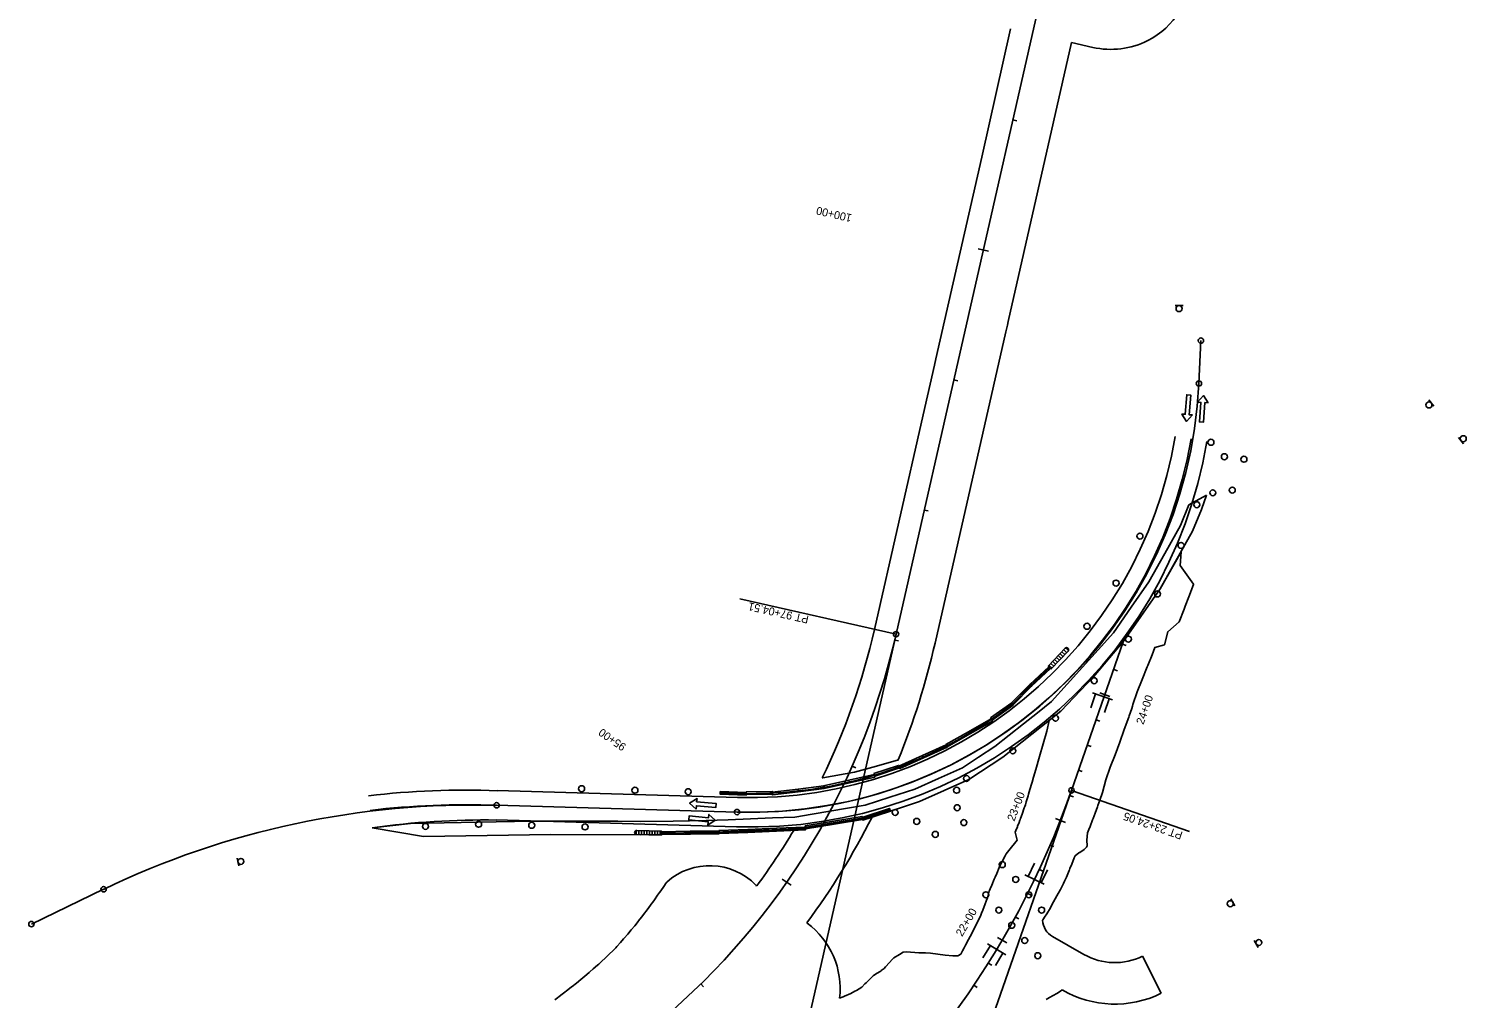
# Model space of a CAD drawing. Extents: x 1710760 to 1712674, y 548603 to 551129.
# Drawn here: x 1711597 to 1712674, y 549354 to 550081 of the extents above; entities that cross this region are included whole.
import ezdxf

# ---------------------------------------------------------------- set-up
doc = ezdxf.new("R2010")
doc.units = 0
for name, color, linetype in [('R_Horz Alg', 7, 'Continuous'), ('R_Horz Alg Annot', 7, 'Continuous'), ('R_MOT', 7, 'Continuous'), ('R_No Plot', 7, 'Continuous'), ('R_Striping', 7, 'Continuous')]:
    doc.layers.add(name, color=color, linetype=linetype)

msp = doc.modelspace()

# ---------------------------------------------------------------- linework, layer by layer
at = {"layer": 'R_Horz Alg'}
for p, q in [((1712246.8, 549627.3), (1712450.8, 550525.8)), ((1712246.8, 549627.3), (1712450.8, 550525.8)), ((1712473.8, 549815.3), (1712475.3, 549847.4)), ((1712378.3, 549510.2), (1712417.1, 549621.6)), ((1711947.4, 549499), (1712127.6, 549493.9)), ((1711598.7, 549409.9), (1711652.8, 549436))]:
    msp.add_line(p, q, dxfattribs=at)
for centre, radius, start, end in [((1712137.1, 549830.8), 337, 268.3826, 357.3716), ((1711727, 549745.3), 533, 270.6428, 347.2066), ((1711727, 549745.3), 533, 270.6428, 347.2066), ((1711777.2, 549719.9), 636.6, 271.0787, 340.7734), ((1711929.4, 548862.6), 636.6, 88.3826, 115.7513)]:
    msp.add_arc(centre, radius, start, end, dxfattribs=at)
at = {"layer": 'R_Horz Alg Annot'}
for p, q in [((1712153.6, 549217.1), (1712246.8, 549627.3)), ((1712153.6, 549217.1), (1712246.8, 549627.3)), ((1712232.3, 549091.7), (1712378.3, 549510.2)), ((1712466.6, 549479.4), (1712378.3, 549510.2))]:
    msp.add_line(p, q, dxfattribs=at)
for points in [[(1712337.3, 550012.3), (1712334.3, 550013)], [(1712308.3, 549916.3), (1712316.1, 549914.5)], [(1712293, 549817.3), (1712290.1, 549817.9)], [(1712270.8, 549719.7), (1712267.9, 549720.4)], [(1712246.8, 549627.3), (1712129.8, 549653.9)], [(1712248.7, 549622.2), (1712245.8, 549622.9)], [(1712419.3, 549618.7), (1712416.5, 549619.7)], [(1712412.7, 549599.8), (1712409.9, 549600.8)], [(1712399.5, 549583.3), (1712407.1, 549580.6)], [(1712399.5, 549562.1), (1712396.7, 549563.1)], [(1712393, 549543.2), (1712390.1, 549544.2)], [(1712216.6, 549527.1), (1712213.8, 549528.3)], [(1712386.4, 549524.3), (1712383.5, 549525.3)], [(1712379.8, 549505.4), (1712376.9, 549506.4)], [(1712366.2, 549489.1), (1712373.7, 549486.2)], [(1712365.1, 549468), (1712362.4, 549469.2)], [(1712356.9, 549449.7), (1712354.2, 549450.9)], [(1712161.5, 549443.6), (1712168.1, 549439)], [(1712348.1, 549431.6), (1712345.5, 549432.9)], [(1712338.8, 549413.8), (1712336.2, 549415.2)], [(1712322.9, 549399.8), (1712329.8, 549395.8)], [(1712318.5, 549379.1), (1712315.9, 549380.7)], [(1712102.5, 549362.8), (1712100.4, 549365)], [(1712307.5, 549362.3), (1712305, 549364)]]:
    msp.add_lwpolyline(points, dxfattribs=at)
for centre in [(1712475.3, 549847.4), (1712473.8, 549815.3), (1712246.8, 549627.3), (1712246.8, 549627.3), (1712378.3, 549510.2), (1711947.4, 549499), (1712127.6, 549493.9), (1711652.8, 549436), (1711598.7, 549409.9)]:
    msp.add_circle(centre, 2, dxfattribs=at)
at = {"layer": 'R_MOT'}
for p, q in [((1712311, 549985), (1712332.5, 550081.3)), ((1712311, 549985), (1712332.5, 550081.3)), ((1712378.3, 550070.9), (1712364.8, 550011.4)), ((1712378.3, 550070.9), (1712364.8, 550011.4)), ((1712394.2, 550067.3), (1712378.3, 550070.9)), ((1712394.2, 550067.3), (1712378.3, 550070.9)), ((1712364.8, 550011.4), (1712330.8, 549861.8)), ((1712364.8, 550011.4), (1712330.8, 549861.8)), ((1712276.6, 549833.7), (1712311, 549985)), ((1712276.6, 549833.7), (1712311, 549985)), ((1712455.9, 549873.7), (1712461.9, 549873.7)), ((1712330.8, 549861.8), (1712330.2, 549859)), ((1712330.8, 549861.8), (1712330.2, 549859)), ((1712329.1, 549854.1), (1712276, 549620.6)), ((1712329.1, 549854.1), (1712276, 549620.6)), ((1712330.2, 549859), (1712329.1, 549854.1)), ((1712330.2, 549859), (1712329.1, 549854.1)), ((1712267.1, 549791.8), (1712275.6, 549828.9)), ((1712267.1, 549791.8), (1712275.6, 549828.9)), ((1712275.6, 549828.9), (1712276.6, 549833.7)), ((1712275.6, 549828.9), (1712276.6, 549833.7)), ((1712646, 549803), (1712649.8, 549798.4)), ((1712230.6, 549630.9), (1712267.1, 549791.8)), ((1712230.6, 549630.9), (1712267.1, 549791.8)), ((1712672.1, 549770.1), (1712668.3, 549774.8)), ((1712466.2, 549724.2), (1712479.4, 549731.6)), ((1712466.2, 549724.2), (1712479.4, 549731.6)), ((1712460.4, 549689.1), (1712459.7, 549678.8)), ((1712369.7, 549612.6), (1712371.9, 549610.6)), ((1712371.1, 549614.1), (1712373.3, 549612.1)), ((1712372.5, 549615.6), (1712374.6, 549613.5)), ((1712373.9, 549617), (1712376, 549615)), ((1712347.4, 549588.6), (1712362, 549602.2)), ((1712361.5, 549603.9), (1712363.7, 549601.8)), ((1712362.9, 549605.4), (1712365.1, 549603.3)), ((1712364.3, 549606.8), (1712366.4, 549604.8)), ((1712365.6, 549608.3), (1712367.8, 549606.2)), ((1712367, 549609.7), (1712369.2, 549607.7)), ((1712368.4, 549611.2), (1712370.5, 549609.1)), ((1712333.2, 549574.3), (1712347.4, 549588.6)), ((1712392.7, 549572.2), (1712396.3, 549582.5)), ((1712409, 549578), (1712393.9, 549583.3)), ((1712333.2, 549574.3), (1712333.2, 549574.3)), ((1712402.9, 549568.6), (1712406.5, 549578.9)), ((1712115, 549508.3), (1712128, 549507.9)), ((1712051.9, 549480), (1712051.9, 549477.2)), ((1712053.9, 549480), (1712053.9, 549477)), ((1712055.9, 549480), (1712055.9, 549477)), ((1712057.9, 549479.9), (1712057.9, 549476.9)), ((1712059.9, 549479.9), (1712059.9, 549476.9)), ((1712061.9, 549479.8), (1712061.9, 549476.8)), ((1712063.9, 549479.8), (1712063.9, 549476.8)), ((1712065.9, 549479.7), (1712065.9, 549476.7)), ((1712067.9, 549479.7), (1712067.9, 549476.7)), ((1712069.9, 549479.6), (1712069.9, 549476.6)), ((1712331.3, 549465.1), (1712337.6, 549472.9)), ((1711754.2, 549453.5), (1711752.9, 549459.4)), ((1712350.5, 549455.5), (1712345.7, 549445.6)), ((1712360.3, 549450.7), (1712355.5, 549440.9)), ((1712343.4, 549446.8), (1712357.8, 549439.8)), ((1712141.8, 549438.9), (1712142.4, 549438.5)), ((1712497.7, 549428.9), (1712500.8, 549423.7)), ((1712179.9, 549410.8), (1712180.1, 549410.6)), ((1712364.1, 549400.6), (1712387.6, 549387.2)), ((1712518.3, 549392.4), (1712515.2, 549397.5)), ((1712311.9, 549384.5), (1712317.5, 549393.8)), ((1712329.1, 549386.9), (1712315.4, 549395.1)), ((1712321.2, 549378.9), (1712326.8, 549388.2)), ((1712431.6, 549385.9), (1712445.4, 549358))]:
    msp.add_line(p, q, dxfattribs=at)
for points in [[(1712468.9, 549791.7), (1712464.5, 549786.9), (1712461, 549792.4), (1712463.5, 549792.2), (1712464.7, 549806.8), (1712467.7, 549806.6), (1712466.4, 549791.9)], [(1712480.8, 549800.7), (1712477.2, 549806.2), (1712472.8, 549801.3), (1712475.3, 549801.1), (1712474.1, 549786.5), (1712477.1, 549786.2), (1712478.3, 549800.9)], [(1712347, 549589.6), (1712361.3, 549602.9), (1712362.6, 549601.5), (1712348.4, 549588.2)], [(1712333.2, 549575.8), (1712347, 549589.6), (1712348.4, 549588.2), (1712334.6, 549574.4)], [(1712317.5, 549564.5), (1712333.5, 549575.8), (1712334.6, 549574.2), (1712318.7, 549562.9)], [(1712301.2, 549554.2), (1712318.1, 549563.9), (1712319, 549562.2), (1712302.1, 549552.5)], [(1712284.2, 549544.5), (1712301.2, 549554.2), (1712302.1, 549552.5), (1712285.2, 549542.8)], [(1712248.8, 549528.4), (1712266.6, 549536.4), (1712267.4, 549534.6), (1712249.6, 549526.7)], [(1712266.6, 549536.4), (1712284.4, 549544.3), (1712285.2, 549542.6), (1712267.4, 549534.6)], [(1712230.2, 549522.8), (1712248.7, 549528.9), (1712249.4, 549527.1), (1712230.9, 549520.9)], [(1712192.5, 549513.5), (1712211.5, 549517.8), (1712212, 549515.9), (1712192.9, 549511.6)], [(1712211.5, 549517.8), (1712230.5, 549522), (1712231, 549520.1), (1712212, 549515.9)], [(1712096.9, 549496.1), (1712092, 549500.5), (1712097.6, 549504), (1712097.3, 549501.6), (1712112, 549500.3), (1712111.7, 549497.3), (1712097.1, 549498.6)], [(1712115, 549509.3), (1712134.5, 549508.6), (1712134.5, 549506.7), (1712115, 549507.3)], [(1712134.5, 549509), (1712154, 549509.4), (1712154, 549507.4), (1712134.5, 549507)], [(1712153.9, 549508.8), (1712173.3, 549511.1), (1712173.5, 549509.2), (1712154.1, 549506.8)], [(1712173.3, 549511.1), (1712192.6, 549513.5), (1712192.9, 549511.5), (1712173.5, 549509.2)], [(1712221.3, 549489.9), (1712241.8, 549496.6), (1712242.5, 549494.6), (1712222, 549487.8)], [(1712105.8, 549484.2), (1712111.3, 549487.8), (1712106.5, 549492.2), (1712106.3, 549489.7), (1712091.6, 549491), (1712091.4, 549488), (1712106, 549486.7)], [(1712157.2, 549481.8), (1712178.9, 549482.6), (1712178.9, 549480.5), (1712157.3, 549479.6)], [(1712178.6, 549483.5), (1712200, 549487), (1712200.3, 549484.9), (1712179, 549481.4)], [(1712200, 549487), (1712221.3, 549490.6), (1712221.7, 549488.4), (1712200.3, 549484.9)], [(1712070.8, 549479.2), (1712092.4, 549479.5), (1712092.5, 549477.3), (1712070.9, 549477)], [(1712092.4, 549479.5), (1712114.1, 549479.7), (1712114.1, 549477.6), (1712092.5, 549477.3)], [(1712114, 549480), (1712135.6, 549480.9), (1712135.7, 549478.7), (1712114.1, 549477.8)], [(1712135.6, 549480.9), (1712157.2, 549481.8), (1712157.3, 549479.6), (1712135.7, 549478.7)]]:
    msp.add_lwpolyline(points, close=True, dxfattribs=at)
for points in [[(1712479.4, 549731.6), (1712475.6, 549720.7), (1712469, 549704.5), (1712444.8, 549661.3), (1712417.6, 549622.2), (1712394.7, 549595.2), (1712370.3, 549569.5), (1712326.8, 549535), (1712301.3, 549518.4), (1712264.4, 549501.9), (1712226, 549489.2), (1712171.9, 549480.3), (1712104.7, 549477.5), (1712055.1, 549476.9), (1711988.1, 549477.2), (1711892.6, 549475.7), (1711854.2, 549482.1)], [(1712479.4, 549731.6), (1712466.2, 549724.2)], [(1711854.2, 549482.1), (1711882.9, 549485.3), (1711895.5, 549485.6), (1711908.2, 549485.9), (1711920.8, 549486.1), (1711933.4, 549486.4), (1711947, 549486.6), (1711960.7, 549486.8), (1711974.4, 549487), (1711988, 549487.2), (1712004.8, 549487.1), (1712021.5, 549487.1), (1712038.3, 549487), (1712055, 549486.9), (1712079.7, 549487.2), (1712104.4, 549487.5), (1712121, 549488.2), (1712137.6, 549488.9), (1712154.2, 549489.6), (1712170.8, 549490.2), (1712184, 549492.4), (1712197.2, 549494.6), (1712210.4, 549496.8), (1712223.6, 549499), (1712242.2, 549505.1), (1712260.8, 549511.2), (1712278.6, 549519.2), (1712296.5, 549527.2), (1712308.7, 549535.2), (1712320.9, 549543.1), (1712331.6, 549551.5), (1712342.2, 549560), (1712352.8, 549568.4), (1712363.4, 549576.8), (1712375, 549589.7), (1712386.6, 549602.6), (1712398.2, 549615.5), (1712409.8, 549628.4), (1712423.1, 549647.5), (1712436.3, 549666.6), (1712448.2, 549687.7), (1712460, 549708.8), (1712466.2, 549724.2)], [(1712361.6, 549562.6), (1712370.3, 549569.5), (1712394.7, 549595.2), (1712417.6, 549622.2), (1712444.8, 549661.3), (1712460.4, 549689.1)], [(1712459.7, 549678.8), (1712469.8, 549664.7), (1712469.8, 549664.6), (1712466.3, 549655.3), (1712463.5, 549648.2), (1712462.7, 549646), (1712459.1, 549636.6), (1712450.4, 549629.1), (1712448.1, 549619.3)], [(1712448.1, 549619.3), (1712440.7, 549617.4), (1712438.8, 549611.9), (1712435.4, 549603.8), (1712435, 549602.7), (1712431.2, 549593.4), (1712427.5, 549584.1), (1712424.3, 549574.6), (1712424.3, 549574.5), (1712424, 549573.4), (1712423.4, 549571.6), (1712421.6, 549566.2), (1712421.2, 549565.1), (1712417.7, 549555.8), (1712414.4, 549546.3), (1712410.9, 549536.9), (1712407.3, 549527.6), (1712404.1, 549518.1), (1712401.4, 549508.5), (1712399.5, 549502.9), (1712398.1, 549498.9), (1712397.7, 549497.9), (1712395.9, 549493), (1712394.5, 549489.2), (1712394.1, 549488.1), (1712392.2, 549483.2), (1712391.3, 549480.8), (1712390.8, 549479.5), (1712390.3, 549478.3), (1712389.8, 549472.9), (1712389.9, 549468.7), (1712389.4, 549467.7), (1712389.3, 549467.4), (1712389.3, 549467.4), (1712387.7, 549465.9), (1712384.5, 549463.7), (1712384.3, 549463.6), (1712383.9, 549463.3), (1712383.9, 549463.3), (1712381, 549461.2), (1712380.4, 549459.7), (1712378.5, 549454.9), (1712377.1, 549451.6), (1712376.7, 549450.7), (1712376.5, 549450.1), (1712374.5, 549445.2), (1712373.1, 549442.1), (1712372.4, 549440.4), (1712370, 549435.8), (1712368.4, 549432.9), (1712367.4, 549431.2), (1712364.9, 549426.7), (1712363.4, 549423.8), (1712362.5, 549422), (1712359.8, 549417.7), (1712359.7, 549417.6), (1712358.1, 549415), (1712357.3, 549413.8), (1712356.9, 549413.2), (1712356.6, 549412.8)], [(1712373.5, 549616.7), (1712360.9, 549603.2), (1712363.1, 549601.2), (1712375.7, 549614.6)], [(1712337.6, 549472.9), (1712336.1, 549478.9), (1712336.6, 549480.2), (1712337.7, 549482.8), (1712337.7, 549482.9), (1712337.8, 549483.2), (1712337.9, 549483.4), (1712339, 549486.2), (1712339.6, 549487.9), (1712339.6, 549487.9), (1712339.7, 549488.1), (1712340.1, 549489.1), (1712341.2, 549492.4), (1712342.8, 549497), (1712343.2, 549498.1), (1712343.7, 549499.4), (1712344.4, 549501.6), (1712345.8, 549506.2), (1712346.1, 549507.3), (1712347.1, 549510.9), (1712348.5, 549515.5), (1712348.8, 549516.4), (1712349.8, 549520.2), (1712351.5, 549525.9), (1712354.2, 549535.5), (1712357, 549545.1), (1712359.8, 549554.7), (1712361.6, 549562.6)], [(1712248.5, 549533.1), (1712232.1, 549528.4), (1712215.7, 549523.8), (1712191.9, 549519.6), (1712191.4, 549519.5)], [(1712248.5, 549533.1), (1712232.1, 549528.4), (1712215.7, 549523.8), (1712191.9, 549519.6), (1712191.4, 549519.5)], [(1712242.2, 549495.6), (1712225.7, 549490.2), (1712171.8, 549481.3), (1712104.7, 549478.5), (1712070.8, 549478.1)], [(1712170.2, 549480.2), (1712171.9, 549480.3), (1712226, 549489.2), (1712228.9, 549490.2)], [(1712052.4, 549480.1), (1712070.9, 549479.6), (1712070.8, 549476.6), (1712052.3, 549477.1)], [(1712293.1, 549386), (1712295.3, 549387.4), (1712296.6, 549389.8), (1712297.9, 549392.1), (1712298.9, 549394.1), (1712301.2, 549398.4), (1712302.4, 549400.6), (1712303.5, 549402.8), (1712305.7, 549407.1), (1712306.8, 549409.3), (1712307.9, 549411.5), (1712310, 549415.9), (1712310.9, 549418), (1712311.9, 549420.4), (1712313.6, 549425.1), (1712314.4, 549427.1), (1712314.6, 549427.9), (1712315.3, 549429.7), (1712316.6, 549434.5), (1712316.9, 549435.1), (1712317.4, 549436.4), (1712318.5, 549439), (1712318.5, 549439.1), (1712320.3, 549443.5), (1712321.1, 549445.2), (1712322.2, 549447.9), (1712324.1, 549452.4), (1712324.8, 549454.1), (1712326.3, 549456.8), (1712328.5, 549461), (1712329.3, 549462.5), (1712331.3, 549465.1)], [(1712036.7, 549392.2), (1712037.6, 549393.2), (1712040.3, 549396.2), (1712042.5, 549398.8), (1712043, 549399.3), (1712045.7, 549402.4), (1712048.3, 549405.6), (1712048.3, 549405.6), (1712050.9, 549408.7), (1712053.4, 549411.9), (1712053.8, 549412.4), (1712056, 549415.1), (1712058.5, 549418.3), (1712059.2, 549419.4), (1712060.9, 549421.6), (1712063.3, 549424.9), (1712064.5, 549426.4), (1712065.7, 549428.2), (1712068, 549431.5), (1712069.5, 549433.6), (1712070.4, 549434.8), (1712072.7, 549438.1), (1712074.5, 549440.8), (1712074.9, 549441.4)], [(1711991, 549353.2), (1711993.1, 549354.7), (1711994.3, 549355.7), (1711996.6, 549357.4), (1711997.6, 549358.1), (1712000.9, 549360.6), (1712003.6, 549362.8), (1712004.1, 549363.1), (1712007.3, 549365.7), (1712010.5, 549368.3), (1712010.5, 549368.3), (1712013.6, 549370.9), (1712016.7, 549373.6), (1712017.3, 549374.1), (1712019.8, 549376.3), (1712022.9, 549379), (1712023.9, 549379.9), (1712025.9, 549381.8), (1712028.9, 549384.6), (1712030.4, 549386), (1712031.8, 549387.4), (1712034.7, 549390.2), (1712036.7, 549392.2)], [(1712204.5, 549354.4), (1712207.1, 549355.4), (1712208.2, 549355.9), (1712212.8, 549357.9), (1712216, 549359.5), (1712217.1, 549360.2), (1712221.2, 549362.7), (1712223.5, 549365), (1712224.3, 549365.8), (1712224.4, 549365.9), (1712227.6, 549369.2), (1712229.8, 549371.4), (1712229.8, 549371.4), (1712231.1, 549372.2), (1712232.1, 549372.8), (1712235.3, 549374.7), (1712235.7, 549375), (1712237.8, 549376.6), (1712238.8, 549377.8), (1712241.9, 549381.2), (1712243.9, 549383.4), (1712245.2, 549384.5), (1712249.4, 549387.1), (1712252, 549388.8), (1712254.7, 549389.1), (1712263.9, 549388.4), (1712264.5, 549388.4), (1712268.8, 549388.4), (1712272.7, 549388.1), (1712283.6, 549386.6), (1712289.4, 549386.1), (1712293.1, 549386)], [(1712371.4, 549360.6), (1712370.1, 549359.5), (1712367.4, 549357.8), (1712361.8, 549354.8), (1712359.4, 549353.4)]]:
    msp.add_lwpolyline(points, dxfattribs=at)
for centre in [(1712458.9, 549871.4), (1712646.2, 549799.2), (1712482.8, 549771.2), (1712671.9, 549773.9), (1712492.9, 549760.4), (1712507.5, 549758.5), (1712484.2, 549733.3), (1712498.8, 549735.3), (1712472.2, 549724.4), (1712429.6, 549700.8), (1712460.4, 549693.8), (1712411.7, 549665.6), (1712442.7, 549657.5), (1712389.9, 549633.2), (1712420.9, 549623.6), (1712395.3, 549592.4), (1712366.3, 549564.3), (1712334.3, 549539.8), (1712299.6, 549519.1), (1712011.1, 549511.4), (1712051.1, 549510.3), (1712091, 549509.2), (1712292.2, 549510.3), (1712246.1, 549493.6), (1712292.6, 549497.2), (1711894.1, 549483.2), (1711933.9, 549484.8), (1711973.7, 549484), (1712013.7, 549482.8), (1712262.3, 549486.9), (1712297.6, 549486), (1712276.2, 549477.2), (1711755.7, 549456.9), (1712326.4, 549454.5), (1712336.5, 549443.4), (1712314.1, 549431.9), (1712346.3, 549431.9), (1712323.8, 549420.4), (1712355.9, 549420.4), (1712497.3, 549425.2), (1712333.5, 549409), (1712343.2, 549397.6), (1712518.7, 549396.1), (1712353, 549386.2)]:
    msp.add_circle(centre, 2.25, dxfattribs=at)
for centre, radius, start, end in [((1712407.7, 550126.9), 61.1, 297.0662, 358.1873), ((1712407.7, 550126.9), 61.1, 297.0662, 358.1873), ((1712407.7, 550126.9), 61.1, 257.2066, 297.0662), ((1712407.7, 550126.9), 61.1, 257.2066, 297.0662), ((1711727, 549745.3), 516.4, 334.0724, 347.196), ((1711727, 549745.3), 516.4, 334.0724, 347.196), ((1711727, 549745.3), 563, 337.855, 347.1969), ((1711727, 549745.3), 563, 337.855, 347.1969), ((1712374.6, 549615.7), 1.5, 316.843, 136.843), ((1712137.4, 549828.7), 321, 268.3287, 307.5861), ((1711727, 549745.3), 563, 323.5493, 333.0539), ((1712052.3, 549478.6), 1.5, 88.472, 268.472), ((1711727, 549745.3), 516.4, 323.5492, 329.11), ((1712107.1, 549405.4), 48.3, 44.026, 131.674), ((1712143.9, 549361.5), 61, 353.3207, 53.5498), ((1712371.5, 549413.5), 14.9, 182.8301, 240.3288), ((1712410.8, 549427.9), 46.9, 240.3288, 296.3424), ((1712410.8, 549427.9), 78, 239.6523, 296.3424)]:
    msp.add_arc(centre, radius, start, end, dxfattribs=at)
at = {"layer": 'R_No Plot'}
for p, q in [((1712347.4, 549588.6), (1712362, 549602.2)), ((1712333.2, 549574.3), (1712347.4, 549588.6)), ((1712333.2, 549574.3), (1712333.2, 549574.3)), ((1712115, 549508.3), (1712128, 549507.9))]:
    msp.add_line(p, q, dxfattribs=at)
msp.add_lwpolyline([(1712242.2, 549495.6), (1712225.7, 549490.2), (1712171.8, 549481.3), (1712104.7, 549478.5), (1712070.8, 549478.1)], dxfattribs=at)
msp.add_arc((1712137.4, 549828.7), 321, 268.3287, 307.5861, dxfattribs=at)
at = {"layer": 'R_Striping'}
for p, q in [((1711947.7, 549510), (1712127.9, 549504.9)), ((1712127.6, 549493.9), (1711947.4, 549499)), ((1711947, 549488), (1712127.3, 549482.9))]:
    msp.add_line(p, q, dxfattribs=at)
for centre, radius, start, end in [((1712137.4, 549828.7), 335, 268.3287, 350.5465), ((1712136.8, 549828.2), 323.5, 268.4304, 350.6481), ((1712138, 549829.2), 346.5, 268.2354, 350.4532), ((1711924.3, 548886.3), 624.1, 87.8473, 96.7132), ((1711924.3, 548886.3), 613.1, 87.8473, 96.7132), ((1711938.1, 548886.1), 601.9, 89.1478, 98.0137)]:
    msp.add_arc(centre, radius, start, end, dxfattribs=at)

# ---------------------------------------------------------------- texts
at = {"layer": 'R_Horz Alg Annot'}
for s, rotation, p in [('100+00', 167.2066, (1712214.1, 549942)), ('PT 97+04.51', 167.2066, (1712181.8, 549641)), ('24+00', 70.7734, (1712432.2, 549559.1)), ('95+00', 145.2214, (1712045, 549544.2)), ('23+00', 68.6088, (1712335.4, 549486.6)), ('PT 23+24.05', 160.7734, (1712462.1, 549478.8)), ('22+00', 59.6088, (1712296.3, 549400.1))]:
    msp.add_text(s, height=6, rotation=rotation, dxfattribs=at).set_placement(p)

doc.saveas('drawing.dxf')
